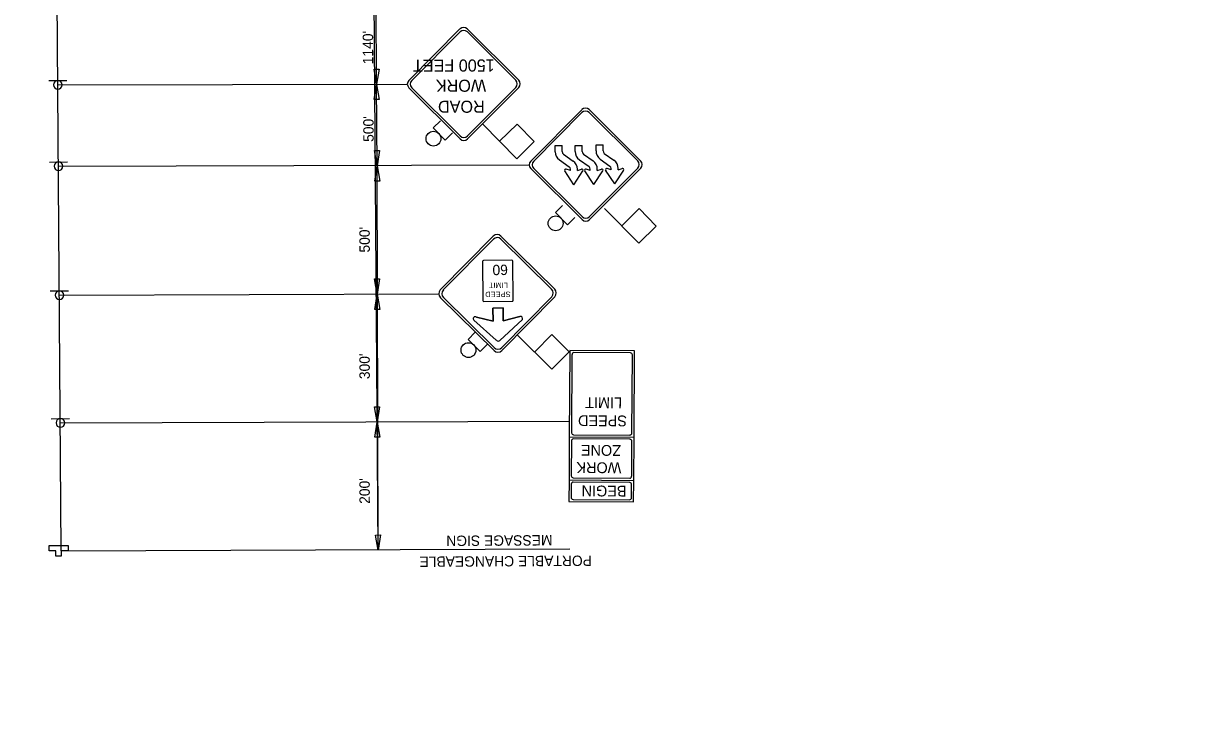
# Model space of a CAD drawing. Extents: x 2135767 to 2151731, y 141839 to 175894.
# Drawn here: x 2140585 to 2141258, y 170330 to 170737 of the extents above; entities that cross this region are included whole.
import ezdxf

# ---------------------------------------------------------------- set-up
doc = ezdxf.new("R2010")
doc.units = 0
for name, color, linetype in [('5', 7, 'Continuous'), ('Default', 7, 'Continuous'), ('PR_Dimensions', 7, 'Continuous'), ('PR_Dimensions_Phase', 7, 'Continuous'), ('PR_Phasing_Detour_1', 7, 'Continuous'), ('PR_Traffic_Control_Devices_Temp', 7, 'Continuous'), ('PR_Txt', 7, 'Continuous')]:
    doc.layers.add(name, color=color, linetype=linetype)

# ---------------------------------------------------------------- blocks, each defined once
blk = doc.blocks.new('PR-TCSIGN')
at = {"layer": 'Default'}
blk.add_line((17.8, 8.5), (-17.8, 8.5), dxfattribs=at)
blk.add_circle((0, 0), 8.47, dxfattribs=at)
blk = doc.blocks.new('PR-TCSIGN_rev')
at = {"layer": 'Default'}
blk.add_lwpolyline([(-5.47, 0), (-1.58, 0), (-1.58, -3.22), (1.58, -3.22), (1.58, 0), (5.47, 0), (5.47, 3.06), (-5.47, 3.06)], close=True, dxfattribs=at)
blk.add_lwpolyline([(1.58, 0), (5.47, 0), (5.47, 3.06), (-5.47, 3.06), (-5.47, 0), (-1.58, 0), (-1.58, -3.22), (1.58, -3.22), (1.58, 0)], dxfattribs=at)
blk = doc.blocks.new('Arrowhd')
at = {"layer": 'Default'}
blk.add_lwpolyline([(0.318, -0.053), (0.318, 0.053), (0, 0)], close=True, dxfattribs=at)
blk = doc.blocks.new('R2-1E')
at = {"layer": 'Default'}
for p, q in [((7.62, 10.16), (0, 10.16)), ((0, 10.16), (0, 0)), ((0.25, 9.68), (0.25, 0.48)), ((7.14, 9.91), (0.48, 9.91)), ((7.37, 0.48), (7.37, 9.68)), ((7.62, 0), (7.62, 10.16)), ((0, 0), (7.62, 0)), ((0.48, 0.25), (7.14, 0.25))]:
    blk.add_line(p, q, dxfattribs=at)
for centre, start, end in [((0.48, 9.68), 90, 180), ((7.14, 9.68), 0, 90), ((0.48, 0.48), 180, 270), ((7.14, 0.48), 270, 0)]:
    blk.add_arc(centre, 0.222, start, end, dxfattribs=at)
for s, p in [('SPEED', (0.85, 7.62)), ('LIMIT', (1.44, 5.5))]:
    blk.add_text(s, height=1.27, dxfattribs=at).set_placement(p)
blk = doc.blocks.new('CS-14E')
at = {"layer": 'Default'}
for p, q in [((7.62, 2.54), (0, 2.54)), ((0, 2.54), (0, -2.54)), ((0.25, 2.06), (0.25, -2.06)), ((7.14, 2.29), (0.48, 2.29)), ((7.37, -2.06), (7.37, 2.06)), ((7.62, -2.54), (7.62, 2.54)), ((7.62, -2.54), (0, -2.54)), ((0.48, -2.29), (7.14, -2.29))]:
    blk.add_line(p, q, dxfattribs=at)
for centre, start, end in [((0.48, 2.06), 90, 180), ((7.14, 2.06), 0, 90), ((0.48, -2.06), 180, 270), ((7.14, -2.06), 270, 0)]:
    blk.add_arc(centre, 0.222, start, end, dxfattribs=at)
for s, p in [('WORK', (1.48, 0.44)), ('ZONE', (1.53, -1.6))]:
    blk.add_text(s, height=1.27, dxfattribs=at).set_placement(p)
blk = doc.blocks.new('CS-13E')
at = {"layer": 'Default'}
for p, q in [((0, 2.54), (0, 0)), ((7.62, 2.54), (0, 2.54)), ((0.25, 2.06), (0.25, 0.48)), ((7.14, 2.29), (0.48, 2.29)), ((7.37, 0.48), (7.37, 2.06)), ((7.62, 0), (7.62, 2.54)), ((7.62, 0), (0, 0)), ((0.48, 0.25), (7.14, 0.25))]:
    blk.add_line(p, q, dxfattribs=at)
for centre, start, end in [((0.48, 2.06), 90, 180), ((7.14, 2.06), 0, 90), ((0.48, 0.48), 180, 270), ((7.14, 0.48), 270, 0)]:
    blk.add_arc(centre, 0.222, start, end, dxfattribs=at)
blk.add_text('BEGIN', height=1.27, dxfattribs=at).set_placement((0.85, 0.64))
blk = doc.blocks.new('W3-5')
at = {"layer": '5'}
for p, q in [((0.81, 7.63), (6.73, 13.56)), ((13.56, 7.63), (7.63, 13.56)), ((6.73, 0.81), (0.81, 6.74)), ((7.63, 0.81), (13.56, 6.74))]:
    blk.add_line(p, q, dxfattribs=at)
for centre, start, end in [((7.18, 13.11), 45, 135), ((1.26, 7.18), 135, 225), ((13.11, 7.18), 315, 45), ((7.18, 1.26), 225, 315)]:
    blk.add_arc(centre, 0.635, start, end, dxfattribs=at)
at = {"layer": 'Default'}
for p, q in [((0.45, 7.63), (6.73, 13.92)), ((13.92, 7.63), (7.63, 13.92)), ((6.95, 12.72), (4.28, 10.3)), ((9.98, 10.32), (7.37, 12.69)), ((5.35, 8.02), (5.35, 3.42)), ((8.8, 8.13), (5.46, 8.13)), ((8.91, 3.42), (8.91, 8.02)), ((6.73, 0.45), (0.45, 6.74)), ((7.63, 0.45), (13.92, 6.74)), ((5.46, 3.3), (8.8, 3.3))]:
    blk.add_line(p, q, dxfattribs=at)
for points in [[(4.28, 10.3), (6.95, 12.72)], [(7.37, 12.69), (9.98, 10.32)], [(4.58, 9.92), (6.55, 10.41), (6.55, 8.91), (7.74, 8.91), (7.74, 10.45), (9.68, 9.96)], [(9.68, 9.96), (7.74, 10.45), (7.74, 8.91), (6.55, 8.91), (6.55, 10.41), (4.58, 9.92)]]:
    blk.add_lwpolyline(points, dxfattribs=at)
for centre, radius, start, end in [((7.18, 13.47), 0.635, 45, 135), ((7.14, 12.51), 0.285, 37.9142, 132.1493), ((7.14, 12.51), 0.285, 37.9142, 132.1493), ((4.52, 10.19), 0.269, 154.0903, 283.9085), ((4.52, 10.19), 0.269, 154.0903, 283.9085), ((9.83, 10.15), 0.237, 231.3417, 47.9123), ((9.83, 10.15), 0.237, 231.3417, 47.9123), ((0.9, 7.18), 0.635, 135, 225), ((5.46, 8.02), 0.111, 90, 180), ((8.8, 8.02), 0.111, 0, 90), ((13.47, 7.18), 0.635, 315, 45), ((5.46, 3.42), 0.111, 180, 270), ((8.8, 3.42), 0.111, 270, 0), ((7.18, 0.9), 0.635, 225, 315)]:
    blk.add_arc(centre, radius, start, end, dxfattribs=at)
for s, p in [('SPEED', (5.65, 6.99)), ('LIMIT', (5.95, 5.93))]:
    blk.add_text(s, height=0.635, dxfattribs=at).set_placement(p)
blk = doc.blocks.new('FLSHFLAG')
at = {"layer": 'PR_Txt'}
for p, q in [((-1.2, 14.13), (0.84, 16.15)), ((0.84, 16.15), (4.9, 12.08)), ((0.82, 12.08), (-1.2, 14.13)), ((0.82, 12.08), (2.86, 14.11)), ((9.26, 14), (8.4, 13.15)), ((9.26, 14), (10.68, 12.58)), ((10.68, 12.58), (9.83, 11.72))]:
    blk.add_line(p, q, dxfattribs=at)
blk.add_circle((10.65, 13.84), 0.873, dxfattribs=at)
blk = doc.blocks.new('Cw20-1_none')
at = {"layer": 'Default'}
for p, q in [((0.177, 3.005), (2.651, 5.48)), ((0.318, 3.005), (2.651, 5.339)), ((5.48, 3.005), (3.005, 5.48)), ((5.338, 3.005), (3.005, 5.339)), ((2.651, 0.177), (0.177, 2.652)), ((2.651, 0.318), (0.318, 2.652)), ((3.005, 0.177), (5.48, 2.652)), ((3.005, 0.318), (5.338, 2.652))]:
    blk.add_line(p, q, dxfattribs=at)
for centre, start, end in [((2.828, 5.303), 45, 135), ((2.828, 5.162), 45, 135), ((0.353, 2.828), 135, 225), ((0.495, 2.828), 135, 225), ((5.162, 2.828), 315, 45), ((5.303, 2.828), 315, 45), ((2.828, 0.495), 225, 315), ((2.828, 0.354), 225, 315)]:
    blk.add_arc(centre, 0.25, start, end, dxfattribs=at)
for s, p in [('ROAD', (1.821, 3.637)), ('WORK', (1.751, 2.623))]:
    blk.add_text(s, height=0.5833, dxfattribs=at).set_placement(p)

msp = doc.modelspace()

# ---------------------------------------------------------------- linework, layer by layer
at = {"layer": 'PR_Dimensions'}
for p, q in [((2140789.87, 170701.84), (2140789.57, 170749.05)), ((2140790.17, 170654.64), (2140789.87, 170701.84)), ((2140790.74, 170432.11), (2140790.17, 170654.64))]:
    msp.add_line(p, q, dxfattribs=at)
at = {"layer": 'PR_Dimensions_Phase'}
for p, q in [((2140605.21, 170701.53), (2140807.64, 170701.96)), ((2140605.56, 170654.34), (2140878.27, 170655.2)), ((2140606.12, 170579.74), (2140825.83, 170580.53)), ((2140606.68, 170505.74), (2140901.52, 170506.82)), ((2140607.23, 170431.76), (2140901.81, 170432.82))]:
    msp.add_line(p, q, dxfattribs=at)
at = {"layer": 'PR_Phasing_Detour_1'}
msp.add_circle((2140069.54, 171591.41), 4302.23, dxfattribs=at)
at = {"layer": 'PR_Traffic_Control_Devices_Temp'}
for p, q in [((2140607.23, 170431.76), (2140602.86, 171013.91)), ((2140790.79, 170432.42), (2140786.42, 171014.57)), ((2140908.75, 170687.12), (2140879.14, 170657.33)), ((2140908.75, 170685.42), (2140880.84, 170657.33)), ((2140912.99, 170687.14), (2140942.78, 170657.53)), ((2140912.99, 170685.44), (2140941.08, 170657.53)), ((2140893.28, 170666.28), (2140897.34, 170666.29)), ((2140893.29, 170662.8), (2140893.28, 170666.28)), ((2140897.35, 170662.81), (2140897.34, 170666.29)), ((2140904.84, 170666.31), (2140908.9, 170666.33)), ((2140904.84, 170666.31), (2140908.9, 170666.33)), ((2140904.84, 170666.31), (2140908.9, 170666.33)), ((2140904.85, 170662.84), (2140904.84, 170666.31)), ((2140904.85, 170662.84), (2140904.84, 170666.31)), ((2140904.85, 170662.84), (2140904.84, 170666.31)), ((2140908.91, 170662.85), (2140908.9, 170666.33)), ((2140908.91, 170662.85), (2140908.9, 170666.33)), ((2140908.91, 170662.85), (2140908.9, 170666.33)), ((2140916.92, 170666.69), (2140920.98, 170666.7)), ((2140916.93, 170663.21), (2140916.92, 170666.69)), ((2140920.99, 170663.22), (2140920.98, 170666.7)), ((2140920.98, 170666.7), (2140920.98, 170666.7)), ((2140920.98, 170666.7), (2140920.98, 170666.7)), ((2140920.98, 170666.7), (2140920.98, 170666.7)), ((2140920.98, 170666.7), (2140920.98, 170666.7)), ((2140898.08, 170661.4), (2140903.69, 170657.39)), ((2140909.64, 170661.44), (2140915.25, 170657.43)), ((2140909.64, 170661.44), (2140915.25, 170657.43)), ((2140909.64, 170661.44), (2140915.25, 170657.43)), ((2140919.36, 170658.51), (2140924.97, 170654.5)), ((2140921.72, 170661.81), (2140927.33, 170657.8)), ((2140879.16, 170653.09), (2140908.95, 170623.48)), ((2140880.85, 170653.09), (2140908.94, 170625.18)), ((2140895.72, 170658.1), (2140901.33, 170654.09)), ((2140904.12, 170643.69), (2140898.84, 170651.67)), ((2140902.06, 170651.81), (2140899.72, 170652.63)), ((2140902.06, 170651.81), (2140902.06, 170652.68)), ((2140904.12, 170643.69), (2140909.34, 170651.71)), ((2140906.12, 170651.82), (2140906.12, 170652.69)), ((2140906.12, 170651.82), (2140908.46, 170652.66)), ((2140907.28, 170658.14), (2140912.89, 170654.13)), ((2140907.28, 170658.14), (2140912.89, 170654.13)), ((2140907.28, 170658.14), (2140912.89, 170654.13)), ((2140915.67, 170643.73), (2140910.4, 170651.71)), ((2140915.67, 170643.73), (2140910.4, 170651.71)), ((2140915.67, 170643.73), (2140910.4, 170651.71)), ((2140913.62, 170651.84), (2140911.28, 170652.66)), ((2140913.62, 170651.84), (2140911.28, 170652.66)), ((2140913.62, 170651.84), (2140911.28, 170652.66)), ((2140942.8, 170653.29), (2140913.19, 170623.5)), ((2140941.1, 170653.28), (2140913.19, 170625.19)), ((2140913.62, 170651.84), (2140913.62, 170652.72)), ((2140913.62, 170651.84), (2140913.62, 170652.72)), ((2140913.62, 170651.84), (2140913.62, 170652.72)), ((2140915.67, 170643.73), (2140920.9, 170651.74)), ((2140915.67, 170643.73), (2140920.9, 170651.74)), ((2140915.67, 170643.73), (2140920.9, 170651.74)), ((2140917.68, 170651.85), (2140917.68, 170652.73)), ((2140917.68, 170651.85), (2140917.68, 170652.73)), ((2140917.68, 170651.85), (2140917.68, 170652.73)), ((2140917.68, 170651.85), (2140920.02, 170652.69)), ((2140917.68, 170651.85), (2140920.02, 170652.69)), ((2140917.68, 170651.85), (2140920.02, 170652.69)), ((2140927.76, 170644.1), (2140922.48, 170652.09)), ((2140925.7, 170652.22), (2140923.36, 170653.04)), ((2140925.7, 170652.22), (2140925.7, 170653.09)), ((2140927.76, 170644.1), (2140932.99, 170652.12)), ((2140929.77, 170652.23), (2140929.76, 170653.1)), ((2140929.77, 170652.23), (2140932.1, 170653.07))]:
    msp.add_line(p, q, dxfattribs=at)
for centre, radius, start, end in [((2140910.87, 170685.01), 3, 45.1825, 135.1825), ((2140910.88, 170683.31), 3, 45.1825, 135.1825), ((2140899.09, 170662.82), 5.8, 180.1825, 234.45032), ((2140899.09, 170662.82), 1.74, 180.1825, 234.45032), ((2140910.65, 170662.85), 5.8, 180.1825, 234.45032), ((2140910.65, 170662.85), 5.8, 180.1825, 234.45032), ((2140910.65, 170662.85), 5.8, 180.1825, 234.45032), ((2140910.65, 170662.85), 1.74, 180.1825, 234.45032), ((2140910.65, 170662.85), 1.74, 180.1825, 234.45032), ((2140910.65, 170662.85), 1.74, 180.1825, 234.45032), ((2140922.73, 170663.23), 5.8, 180.1825, 234.45032), ((2140922.73, 170663.23), 1.74, 180.1825, 234.45032), ((2140881.27, 170655.21), 3, 135.1825, 225.1825), ((2140882.97, 170655.22), 3, 135.1825, 225.1825), ((2140899.45, 170651.99), 0.689, 67.03344, 219.29911), ((2140900.32, 170652.67), 1.74, 0.1825, 54.45032), ((2140900.32, 170652.67), 5.8, 0.1825, 54.45032), ((2140908.73, 170652.02), 0.689, 321.0659, 113.33156), ((2140911.01, 170652.03), 0.689, 67.03344, 219.29911), ((2140911.01, 170652.03), 0.689, 67.03344, 219.29911), ((2140911.01, 170652.03), 0.689, 67.03344, 219.29911), ((2140911.88, 170652.71), 1.74, 0.1825, 54.45032), ((2140911.88, 170652.71), 1.74, 0.1825, 54.45032), ((2140911.88, 170652.71), 1.74, 0.1825, 54.45032), ((2140911.88, 170652.71), 5.8, 0.1825, 54.45032), ((2140911.88, 170652.71), 5.8, 0.1825, 54.45032), ((2140911.88, 170652.71), 5.8, 0.1825, 54.45032), ((2140920.29, 170652.06), 0.689, 321.0659, 113.33156), ((2140920.29, 170652.06), 0.689, 321.0659, 113.33156), ((2140920.29, 170652.06), 0.689, 321.0659, 113.33156), ((2140923.09, 170652.41), 0.689, 67.03344, 219.29911), ((2140923.96, 170653.09), 1.74, 0.1825, 54.45032), ((2140923.96, 170653.09), 5.8, 0.1825, 54.45032), ((2140932.37, 170652.44), 0.689, 321.0659, 113.33156), ((2140938.97, 170655.4), 3, 315.1825, 45.1825), ((2140940.67, 170655.4), 3, 315.1825, 45.1825), ((2140911.06, 170627.31), 3, 225.1825, 315.1825), ((2140911.06, 170625.61), 3, 225.1825, 315.1825)]:
    msp.add_arc(centre, radius, start, end, dxfattribs=at)

# ---------------------------------------------------------------- block references
at = {"layer": 'PR_Dimensions', "xscale": 27.55900000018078, "yscale": -27.559000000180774}
for p, rotation in [((2140789.87, 170701.84), 90.36501731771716), ((2140789.85, 170701.75), -89.63498268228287), ((2140790.17, 170654.64), 90.36501731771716), ((2140790.15, 170654.55), -89.63498268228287), ((2140790.17, 170580.36), 90.36501731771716), ((2140790.15, 170580.27), -89.63498268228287), ((2140790.17, 170506.39), 90.36501731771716), ((2140790.15, 170506.29), -89.63498268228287), ((2140790.74, 170432.11), 90.36501731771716)]:
    msp.add_blockref('Arrowhd', p, dxfattribs=dict(at, rotation=rotation))
at = {"layer": 'PR_Traffic_Control_Devices_Temp'}
for name, p, xscale, yscale, rotation in [('Cw20-1_none', (2140874.2, 170736.04), 11.999999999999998, 11.999999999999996, -179.8801934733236), ('PR-TCSIGN', (2140605.21, 170701.53), 0.2952750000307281, -0.2952750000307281, -179.6349826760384), ('FLSHFLAG', (2140875.49, 170738.2), 4.92125000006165, 4.92125000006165, 179.7547892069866), ('PR-TCSIGN', (2140605.56, 170654.34), 0.2952750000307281, -0.2952750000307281, -179.6349826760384), ('FLSHFLAG', (2140946.14, 170689.24), 4.921250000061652, 4.92125000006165, 179.8174838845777), ('W3-5', (2140894.98, 170616.39), 4.921250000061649, 4.921250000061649, -179.58167045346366), ('PR-TCSIGN', (2140606.12, 170579.74), 0.2952750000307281, -0.2952750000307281, -179.6349826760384), ('FLSHFLAG', (2140894.98, 170616.39), 4.921250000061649, 4.921250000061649, -179.58167045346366), ('R2-1E', (2140939.28, 170547.5), 4.921250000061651, 4.921250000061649, 179.6349826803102), ('PR-TCSIGN', (2140606.68, 170505.74), 0.2952750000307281, -0.2952750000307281, -179.6349826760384), ('CS-14E', (2140938.88, 170485), 4.921249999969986, 4.921249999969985, 179.6349826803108), ('CS-13E', (2140938.81, 170472.5), 4.92124999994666, 4.921249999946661, 179.6349826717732)]:
    msp.add_blockref(name, p, dxfattribs=dict(at, xscale=xscale, yscale=yscale, rotation=rotation))
at = {"layer": 'PR_Traffic_Control_Devices_Temp', "yscale": -1, "rotation": -180}
msp.add_blockref('PR-TCSIGN_rev', (2140605.65, 170431.76), dxfattribs=at)

# ---------------------------------------------------------------- texts
at = {"layer": 'Default'}
for s, rotation, p in [("1140'", 90.36502, (2140787.9, 170713.41)), ("500'", 90.36502, (2140788.18, 170668.48)), ("500'", 90.36502, (2140785.93, 170604.4)), ("300'", 90.36502, (2140785.93, 170531.11)), ("200'", 90.36502, (2140785.93, 170458.91)), ('MESSAGE SIGN', 180.36502, (2140891.69, 170440.85)), ('PORTABLE CHANGEABLE', 180.36502, (2140914.53, 170429))]:
    msp.add_text(s, height=6, rotation=rotation, dxfattribs=at).set_placement(p)
at = {"layer": 'PR_Traffic_Control_Devices_Temp'}
for s, height, rotation, p in [('1500 FEET', 7, 180.11981, (2140858.23, 170716.22)), ('60', 6, 180.78335, (2140865.85, 170597.42))]:
    msp.add_text(s, height=height, rotation=rotation, dxfattribs=at).set_placement(p)

doc.saveas('drawing.dxf')
